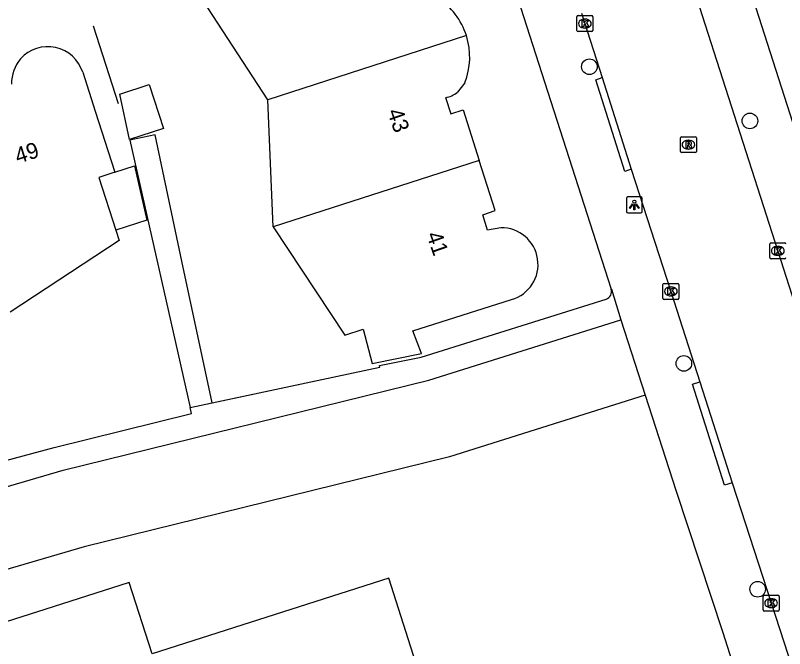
# Model space of a CAD drawing. Extents: x 159503 to 160347, y 382525 to 383272.
# Drawn here: x 159703.39 to 159751.59, y 382799.52 to 382839.21 of the extents above; entities that cross this region are included whole.
import ezdxf

# ---------------------------------------------------------------- set-up
doc = ezdxf.new("R2010")
doc.units = 0
for name, color, linetype in [('IMGEO_Boom', 7, 'Continuous'), ('IMGEO_Groenvoorziening', 7, 'Continuous'), ('IMGEO_Hek', 7, 'Continuous'), ('IMGEO_Kolk', 7, 'Continuous'), ('IMGEO_Lichtpunt', 7, 'Continuous'), ('IMGEO_Muur', 7, 'Continuous'), ('IMGEO_Pand', 7, 'Continuous'), ('IMGEO_Pand_nummerreeks', 7, 'Continuous'), ('IMGEO_Rijbaan_lokaal_open', 7, 'Continuous'), ('IMGEO_Rioolput', 7, 'Continuous'), ('IMGEO_Voetpad_open', 7, 'Continuous')]:
    doc.layers.add(name, color=color, linetype=linetype)

msp = doc.modelspace()

# ---------------------------------------------------------------- linework, layer by layer
at = {"layer": 'IMGEO_Boom'}
for centre in [(159739.356, 382835.995), (159749.414, 382832.597), (159745.276, 382817.397), (159749.901, 382803.244)]:
    msp.add_circle(centre, 0.489, dxfattribs=at)
at = {"layer": 'IMGEO_Groenvoorziening'}
msp.add_lwpolyline([(159742.845, 382815.409), (159730.6, 382811.547), (159707.693, 382805.912), (159674.81, 382796.272), (159673.434, 382801.05)], dxfattribs=at)
at = {"layer": 'IMGEO_Hek'}
msp.add_lwpolyline([(159708.26, 382838.552), (159709.829, 382833.692)], dxfattribs=at)
at = {"layer": 'IMGEO_Kolk'}
for p, q in [((159738.574, 382838.272), (159738.574, 382839.124)), ((159738.649, 382839.198), (159739.501, 382839.198)), ((159739.062, 382838.978), (159739.087, 382838.978)), ((159739.575, 382839.124), (159739.575, 382838.272)), ((159739.501, 382838.198), (159738.649, 382838.198)), ((159739.085, 382838.418), (159739.06, 382838.418)), ((159750.662, 382824.028), (159750.662, 382824.88)), ((159750.737, 382824.954), (159751.589, 382824.954)), ((159751.15, 382824.734), (159751.175, 382824.734)), ((159751.173, 382824.174), (159751.148, 382824.174)), ((159751.589, 382823.954), (159750.737, 382823.954)), ((159743.961, 382821.487), (159743.961, 382822.339)), ((159744.036, 382822.413), (159744.888, 382822.413)), ((159744.449, 382822.193), (159744.474, 382822.193)), ((159744.962, 382822.339), (159744.962, 382821.487)), ((159744.472, 382821.633), (159744.447, 382821.633)), ((159744.888, 382821.413), (159744.036, 382821.413)), ((159750.317, 382802.875), (159751.169, 382802.875)), ((159750.242, 382801.949), (159750.242, 382802.801)), ((159750.73, 382802.655), (159750.755, 382802.655)), ((159751.243, 382802.801), (159751.243, 382801.949)), ((159751.169, 382801.875), (159750.317, 382801.875)), ((159750.753, 382802.095), (159750.728, 382802.095))]:
    msp.add_line(p, q, dxfattribs=at)
for points in [[(159738.574, 382838.272), (159738.574, 382839.124)], [(159738.649, 382839.198), (159739.501, 382839.198)], [(159739.575, 382839.124), (159739.575, 382838.272)], [(159738.895, 382838.898), (159739.018, 382838.898), (159739.018, 382838.747), (159739.148, 382838.898), (159739.312, 382838.898), (159739.166, 382838.747), (159739.319, 382838.498), (159739.167, 382838.498), (159739.082, 382838.662), (159739.018, 382838.595), (159739.018, 382838.498), (159738.895, 382838.498), (159738.895, 382838.898)], [(159739.501, 382838.198), (159738.649, 382838.198)], [(159750.662, 382824.028), (159750.662, 382824.88)], [(159750.737, 382824.954), (159751.589, 382824.954)], [(159750.983, 382824.654), (159751.106, 382824.654), (159751.106, 382824.503), (159751.236, 382824.654), (159751.4, 382824.654), (159751.254, 382824.503), (159751.407, 382824.254), (159751.255, 382824.254), (159751.17, 382824.418), (159751.106, 382824.351), (159751.106, 382824.254), (159750.983, 382824.254), (159750.983, 382824.654)], [(159751.589, 382823.954), (159750.737, 382823.954)], [(159743.961, 382821.487), (159743.961, 382822.339)], [(159744.036, 382822.413), (159744.888, 382822.413)], [(159744.282, 382822.113), (159744.405, 382822.113), (159744.405, 382821.962), (159744.535, 382822.113), (159744.699, 382822.113), (159744.553, 382821.962), (159744.706, 382821.713), (159744.554, 382821.713), (159744.469, 382821.877), (159744.405, 382821.81), (159744.405, 382821.713), (159744.282, 382821.713), (159744.282, 382822.113)], [(159744.962, 382822.339), (159744.962, 382821.487)], [(159744.888, 382821.413), (159744.036, 382821.413)], [(159750.317, 382802.875), (159751.169, 382802.875)], [(159750.242, 382801.949), (159750.242, 382802.801)], [(159750.563, 382802.575), (159750.686, 382802.575), (159750.686, 382802.424), (159750.816, 382802.575), (159750.98, 382802.575), (159750.834, 382802.424), (159750.987, 382802.175), (159750.835, 382802.175), (159750.75, 382802.339), (159750.686, 382802.272), (159750.686, 382802.175), (159750.563, 382802.175), (159750.563, 382802.575)], [(159751.243, 382802.801), (159751.243, 382801.949)], [(159751.169, 382801.875), (159750.317, 382801.875)]]:
    msp.add_lwpolyline(points, dxfattribs=at)
for centre, start, end in [((159738.651, 382839.122), 91.552, 178.448), ((159738.651, 382839.122), 91.552, 178.448), ((159739.499, 382839.122), 1.552, 88.448), ((159739.499, 382839.122), 1.552, 88.448), ((159738.651, 382838.274), 181.552, 268.448), ((159738.651, 382838.274), 181.552, 268.448), ((159739.499, 382838.274), 271.552, 358.448), ((159739.499, 382838.274), 271.552, 358.448), ((159750.739, 382824.878), 91.552, 178.448), ((159750.739, 382824.878), 91.552, 178.448), ((159751.587, 382824.878), 1.552, 88.448), ((159751.587, 382824.878), 1.552, 88.448), ((159750.739, 382824.03), 181.552, 268.448), ((159750.739, 382824.03), 181.552, 268.448), ((159751.587, 382824.03), 271.552, 358.448), ((159751.587, 382824.03), 271.552, 358.448), ((159744.038, 382822.337), 91.552, 178.448), ((159744.038, 382822.337), 91.552, 178.448), ((159744.886, 382822.337), 1.552, 88.448), ((159744.886, 382822.337), 1.552, 88.448), ((159744.038, 382821.489), 181.552, 268.448), ((159744.038, 382821.489), 181.552, 268.448), ((159744.886, 382821.489), 271.552, 358.448), ((159744.886, 382821.489), 271.552, 358.448), ((159750.319, 382802.799), 91.552, 178.448), ((159750.319, 382802.799), 91.552, 178.448), ((159751.167, 382802.799), 1.552, 88.448), ((159751.167, 382802.799), 1.552, 88.448), ((159750.319, 382801.951), 181.552, 268.448), ((159750.319, 382801.951), 181.552, 268.448), ((159751.167, 382801.951), 271.552, 358.448), ((159751.167, 382801.951), 271.552, 358.448)]:
    msp.add_arc(centre, 0.0765, start, end, dxfattribs=at)
for centre, major_axis, ratio, start_param, end_param in [((159739.061, 382838.698), (-0.387, 0.002), 0.722429, 4.712389, 7.853982), ((159739.086, 382838.698), (-0.39, 0.002), 0.717154, 1.570796, 4.712389), ((159751.149, 382824.454), (-0.387, 0.002), 0.722429, 4.712389, 7.853982), ((159751.174, 382824.454), (-0.39, 0.002), 0.717154, 1.570796, 4.712389), ((159744.448, 382821.913), (-0.387, 0.002), 0.722429, 4.712389, 7.853982), ((159744.473, 382821.913), (-0.39, 0.002), 0.717154, 1.570796, 4.712389), ((159750.729, 382802.375), (-0.387, 0.002), 0.722429, 4.712389, 7.853982), ((159750.754, 382802.375), (-0.39, 0.002), 0.717154, 1.570796, 4.712389)]:
    msp.add_ellipse(centre, major_axis=major_axis, ratio=ratio, start_param=start_param, end_param=end_param, dxfattribs=at)
at = {"layer": 'IMGEO_Lichtpunt'}
for p, q in [((159741.674, 382827.734), (159741.674, 382826.927)), ((159741.674, 382827.734), (159741.674, 382826.927)), ((159742.576, 382827.829), (159741.768, 382827.829)), ((159742.576, 382827.829), (159741.768, 382827.829)), ((159742.67, 382826.927), (159742.67, 382827.734)), ((159742.67, 382826.927), (159742.67, 382827.734)), ((159741.768, 382826.833), (159742.576, 382826.833)), ((159741.768, 382826.833), (159742.576, 382826.833))]:
    msp.add_line(p, q, dxfattribs=at)
for points in [[(159742.048, 382827.398), (159742.087, 382827.37), (159741.899, 382827.108), (159741.861, 382827.135), (159742.048, 382827.398)], [(159742.15, 382827.35), (159742.197, 382827.35), (159742.197, 382827.028), (159742.15, 382827.028), (159742.15, 382827.35)], [(159742.26, 382827.37), (159742.298, 382827.397), (159742.485, 382827.135), (159742.446, 382827.107), (159742.26, 382827.37)]]:
    msp.add_lwpolyline(points, dxfattribs=at)
msp.add_circle((159742.173, 382827.532), 0.0994, dxfattribs=at)
for centre, start, end in [((159741.768, 382827.734), 90, 180), ((159741.768, 382827.734), 90, 180), ((159742.576, 382827.734), 0, 90), ((159742.576, 382827.734), 0, 90), ((159741.768, 382826.927), 180, 270), ((159741.768, 382826.927), 180, 270), ((159742.576, 382826.927), 270, 0), ((159742.576, 382826.927), 270, 360)]:
    msp.add_arc(centre, 0.0946, start, end, dxfattribs=at)
at = {"layer": 'IMGEO_Muur'}
msp.add_lwpolyline([(159714.347, 382814.634), (159726.23, 382817.155), (159726.206, 382817.258), (159728.815, 382817.782)], dxfattribs=at)
at = {"layer": 'IMGEO_Pand'}
for points in [[(159719.219, 382833.928), (159714.816, 382840.671)], [(159731.651, 382837.94), (159719.219, 382833.928)], [(159707.609, 382835.645), (159708.389, 382833.209), (159709.618, 382829.381)], [(159709.926, 382834.28), (159711.775, 382834.878), (159712.667, 382832.118), (159710.546, 382831.433), (159709.926, 382834.28)], [(159731.557, 382834.985), (159731.092, 382834.392)], [(159719.547, 382825.96), (159719.219, 382833.928)], [(159730.343, 382834.054), (159730.674, 382833.041), (159731.442, 382833.287), (159732.454, 382830.12)], [(159732.454, 382830.12), (159719.547, 382825.96)], [(159733.805, 382825.903), (159732.976, 382825.755), (159732.671, 382826.718), (159733.457, 382826.98), (159732.454, 382830.12)], [(159709.618, 382829.381), (159708.618, 382829.058), (159709.687, 382825.745)], [(159709.618, 382829.381), (159710.852, 382829.78), (159711.62, 382826.368), (159709.687, 382825.745)], [(159709.687, 382825.745), (159709.894, 382825.104), (159703.068, 382820.615)], [(159719.547, 382825.96), (159724.024, 382819.172), (159725.188, 382819.543), (159725.74, 382817.391), (159728.827, 382818.014), (159728.286, 382819.442), (159734.475, 382821.398)], [(159729.084, 382796.741), (159726.792, 382803.935), (159711.953, 382799.207), (159710.531, 382803.67), (159705.767, 382802.152), (159682.294, 382794.673)]]:
    msp.add_lwpolyline(points, dxfattribs=at)
for centre, radius, start, end in [((159727.428, 382836.586), 4.435, 17.778, 56.9409), ((159727.434, 382836.595), 4.426, 338.668, 17.688), ((159705.42, 382834.957), 2.295, 17.4444, 137.888), ((159705.588, 382834.927), 2.442, 140.0081, 180.4376), ((159730.056, 382835.688), 1.659, 279.9488, 308.6275), ((159733.843, 382823.606), 2.297, 285.9714, 90.9471)]:
    msp.add_arc(centre, radius, start, end, dxfattribs=at)
at = {"layer": 'IMGEO_Rijbaan_lokaal_open'}
for points in [[(159745.694, 382841.502), (159751.166, 382824.443), (159759.246, 382799.219), (159765.262, 382780.583)], [(159738.87, 382839.341), (159740.162, 382835.315)], [(159740.162, 382835.315), (159741.978, 382829.581)], [(159741.978, 382829.581), (159744.463, 382821.914), (159746.286, 382816.242)], [(159746.286, 382816.242), (159748.293, 382809.925)], [(159748.293, 382809.925), (159749.144, 382807.34), (159757.672, 382781.038)]]:
    msp.add_lwpolyline(points, dxfattribs=at)
at = {"layer": 'IMGEO_Rioolput'}
for p, q in [((159745.063, 382830.682), (159745.063, 382831.534)), ((159745.138, 382831.608), (159745.99, 382831.608)), ((159745.551, 382831.388), (159745.576, 382831.388)), ((159746.064, 382831.534), (159746.064, 382830.682)), ((159745.574, 382830.828), (159745.549, 382830.828)), ((159745.99, 382830.608), (159745.138, 382830.608))]:
    msp.add_line(p, q, dxfattribs=at)
for points in [[(159745.063, 382830.682), (159745.063, 382831.534)], [(159745.138, 382831.608), (159745.99, 382831.608)], [(159745.652, 382831.306), (159745.4, 382831.308), (159745.4, 382830.908)], [(159746.064, 382831.534), (159746.064, 382830.682)], [(159745.4, 382830.908), (159745.524, 382830.908), (159745.524, 382831.07), (159745.535, 382831.07)], [(159745.578, 382831.227), (159745.524, 382831.227), (159745.524, 382831.146)], [(159745.524, 382831.146), (159745.576, 382831.146)], [(159745.582, 382831.041), (159745.653, 382830.908), (159745.793, 382830.908), (159745.728, 382831.034)], [(159745.99, 382830.608), (159745.138, 382830.608)]]:
    msp.add_lwpolyline(points, dxfattribs=at)
for centre, radius, start, end in [((159745.14, 382831.532), 0.0765, 91.552, 178.448), ((159745.14, 382831.532), 0.0765, 91.552, 178.448), ((159745.651, 382831.196), 0.109, 350.3612, 89.416), ((159745.988, 382831.532), 0.0765, 1.552, 88.448), ((159745.988, 382831.532), 0.0765, 1.552, 88.448), ((159745.534, 382831.017), 0.0533, 26.0293, 88.6989), ((159745.56, 382831.335), 0.19, 274.7715, 282.9687), ((159745.584, 382831.131), 0.0964, 77.0061, 93.1865), ((159745.598, 382831.188), 0.0378, 276.6634, 79.6772), ((159745.649, 382831.196), 0.112, 277.5842, 350.9817), ((159745.633, 382830.981), 0.108, 29.5134, 73.7905), ((159745.14, 382830.684), 0.0765, 181.552, 268.448), ((159745.14, 382830.684), 0.0765, 181.552, 268.448), ((159745.988, 382830.684), 0.0765, 271.552, 358.448), ((159745.988, 382830.684), 0.0765, 271.552, 358.448)]:
    msp.add_arc(centre, radius, start, end, dxfattribs=at)
for centre, major_axis, ratio, start_param, end_param in [((159745.55, 382831.108), (-0.387, 0.002), 0.722429, 4.712389, 7.853982), ((159745.575, 382831.108), (-0.39, 0.002), 0.717154, 1.570796, 4.712389)]:
    msp.add_ellipse(centre, major_axis=major_axis, ratio=ratio, start_param=start_param, end_param=end_param, dxfattribs=at)
at = {"layer": 'IMGEO_Voetpad_open'}
for points in [[(159759.612, 382809.126), (159732.164, 382894.706)], [(159729.755, 382856.197), (159740.727, 382822.055)], [(159741.978, 382829.581), (159741.573, 382829.435), (159739.751, 382835.181), (159740.162, 382835.315)], [(159715.715, 382814.924), (159713.828, 382823.815), (159712.15, 382831.724), (159710.554, 382831.386), (159714.347, 382814.634)], [(159740.727, 382822.055), (159740.732, 382822.044), (159741.322, 382820.139)], [(159715.715, 382814.924), (159726.23, 382817.155), (159726.206, 382817.258), (159728.815, 382817.782), (159740.402, 382821.43)], [(159673.434, 382801.05), (159706.393, 382810.712), (159729.3, 382816.347), (159741.322, 382820.139)], [(159741.322, 382820.139), (159742.845, 382815.409)], [(159748.293, 382809.925), (159747.817, 382809.774), (159745.81, 382816.091), (159746.286, 382816.242)], [(159742.845, 382815.409), (159744.764, 382809.45), (159747.728, 382800.527), (159763.767, 382750), (159765.793, 382743.617)], [(159714.347, 382814.634), (159715.715, 382814.924)], [(159701.365, 382810.94), (159705.812, 382812.13), (159714.431, 382814.263), (159714.347, 382814.634)]]:
    msp.add_lwpolyline(points, dxfattribs=at)
msp.add_arc((159740.241, 382821.911), 0.507, 288.4855, 16.5657, dxfattribs=at)

# ---------------------------------------------------------------- texts
at = {"layer": 'IMGEO_Pand_nummerreeks'}
for s, rotation, p in [('43', 289.2723, (159726.679, 382833.181)), ('49', 17.7617, (159703.544, 382829.903)), ('41', 289.2741, (159729.126, 382825.467))]:
    msp.add_text(s, height=1, rotation=rotation, dxfattribs=at).set_placement(p)

doc.saveas('drawing.dxf')
